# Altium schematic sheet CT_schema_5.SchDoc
size 309 x 321 mm
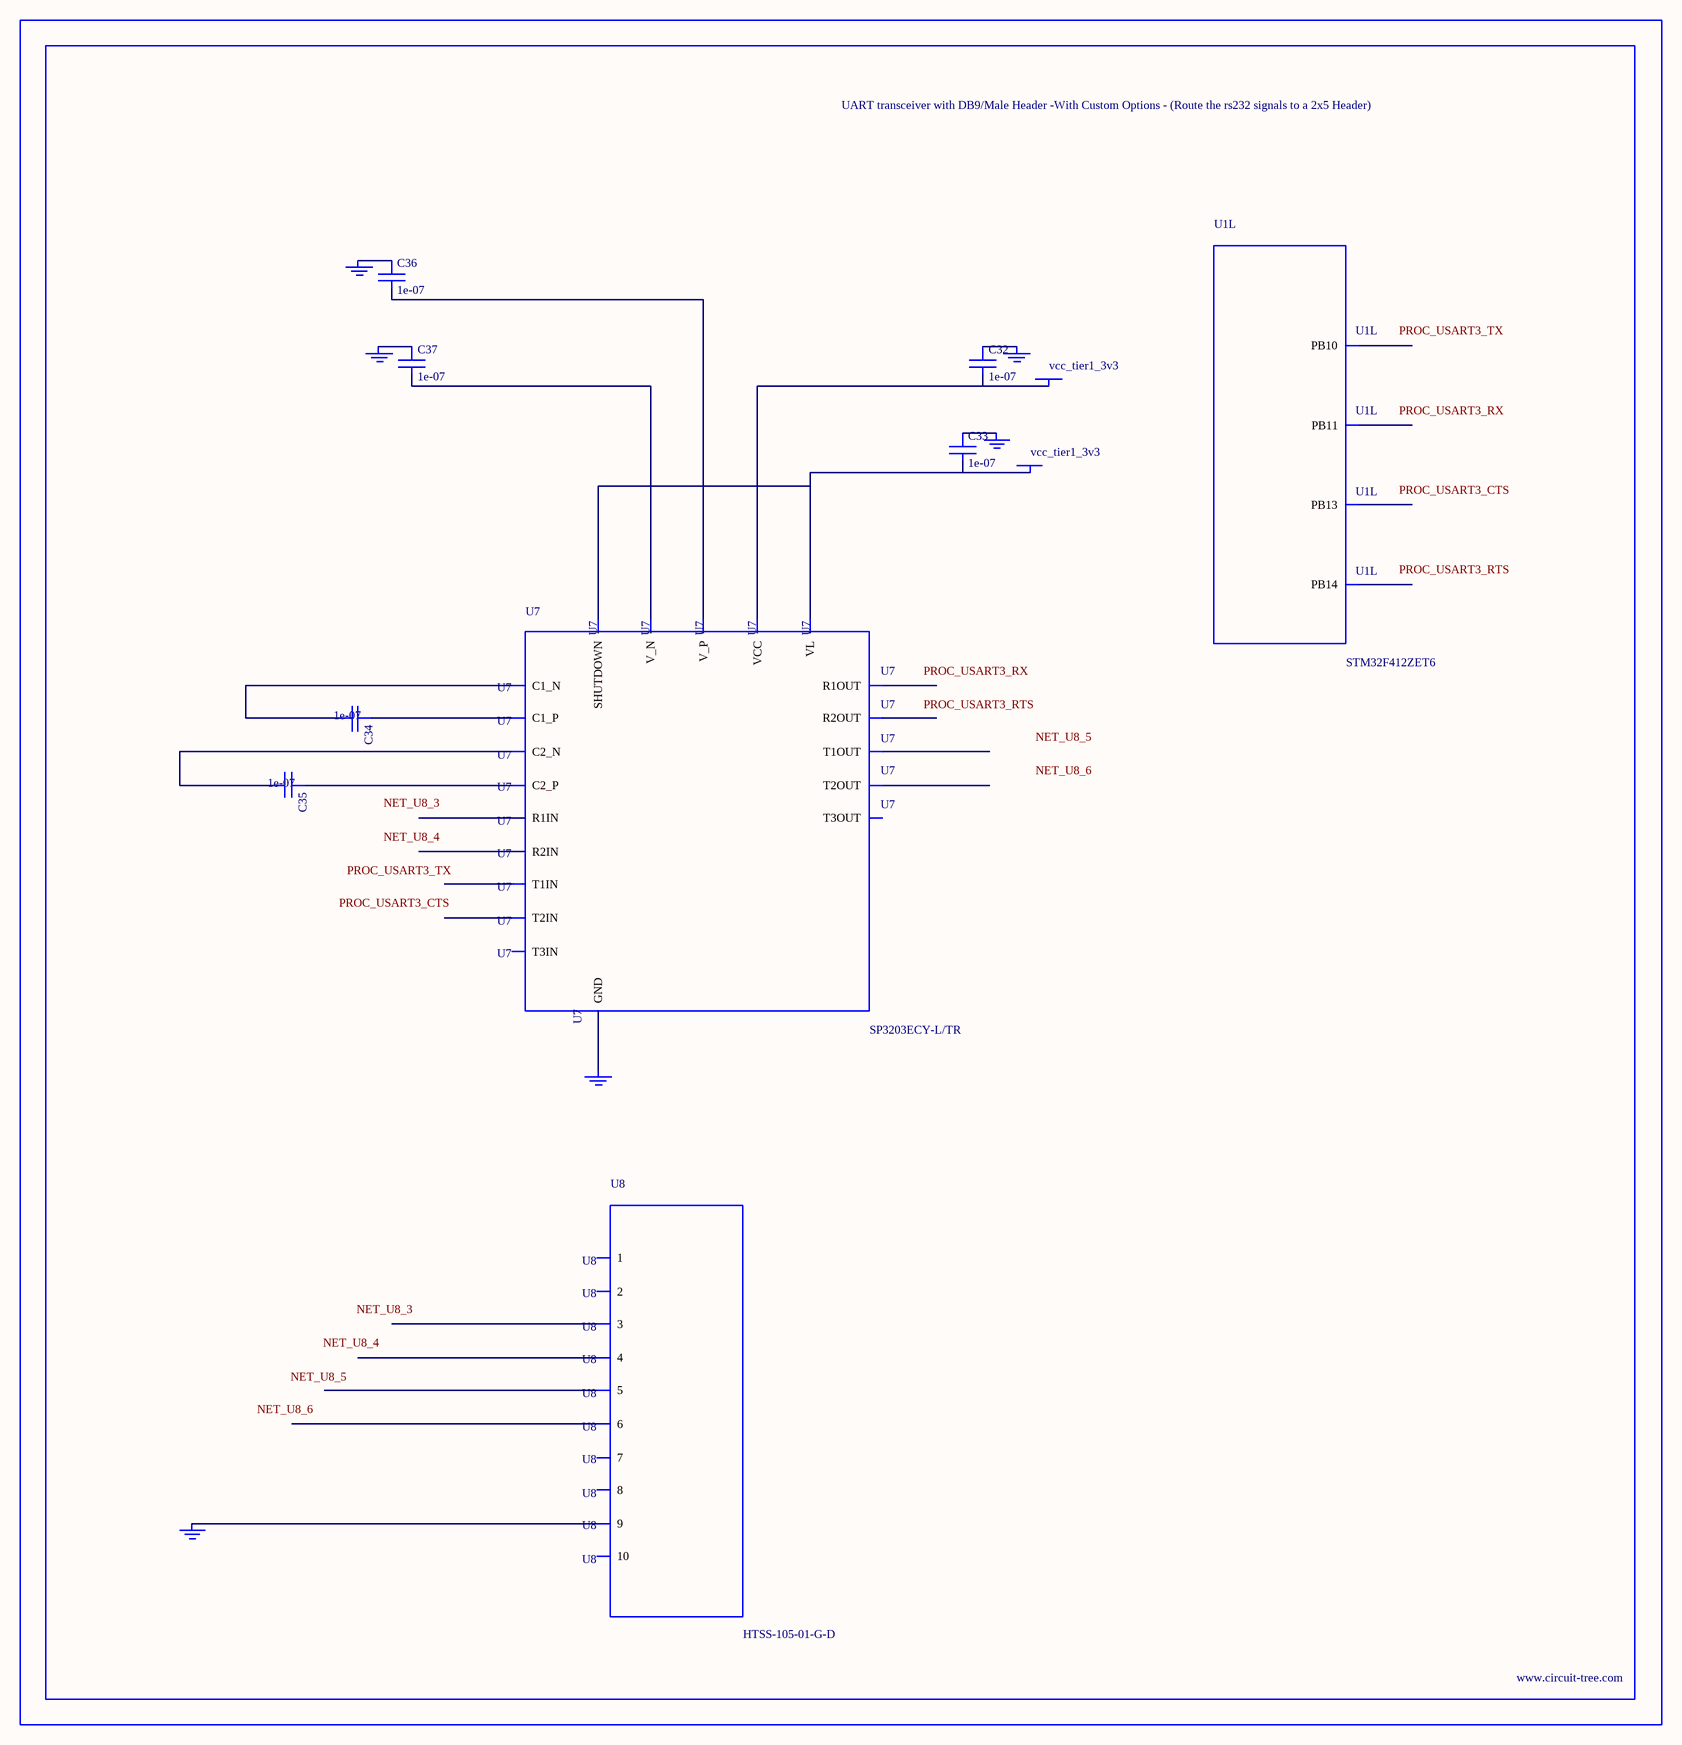
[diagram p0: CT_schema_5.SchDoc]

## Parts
BORDER4  (no value)
C32  1e-07  [C0402]
C33  1e-07  [C0402]
C34  1e-07  [C0402]
C35  1e-07  [C0402]
C36  1e-07  [C0402]
C37  1e-07  [C0402]
GND_INSTANCE_4_0  (no value)
GND_INSTANCE_4_1  (no value)
GND_INSTANCE_4_2  (no value)
GND_INSTANCE_4_3  (no value)
GND_INSTANCE_4_4  (no value)
GND_INSTANCE_4_5  (no value)
POWER_INSTANCE_4_0  vcc_tier1_3v3
POWER_INSTANCE_4_1  vcc_tier1_3v3
U1  STM32F412ZET6  [LQFP144]  (part L of 13)
U7  SP3203ECY-L/TR  [TSSOP20-I]
U8  HTSS-105-01-G-D  [HTSS-105-01-G-D]

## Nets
NetC32_1: C32.1 GND_INSTANCE_4_3.0(GND)
NetC32_2: C32.2 POWER_INSTANCE_4_1.0(PWR) U7.19(VCC)
NetC33_1: C33.1 GND_INSTANCE_4_2.0(GND)
NetC33_2: C33.2 POWER_INSTANCE_4_0.0(PWR) U7.12(VL) U7.20(SHUTDOWN)
NetC34_1: C34.1 U7.1(C1_P)
NetC34_2: C34.2 U7.3(C1_N)
NetC35_1: C35.1 U7.4(C2_P)
NetC35_2: C35.2 U7.5(C2_N)
NetC36_1: C36.1 GND_INSTANCE_4_0.0(GND)
NetC36_2: C36.2 U7.2(V_P)
NetC37_1: C37.1 GND_INSTANCE_4_1.0(GND)
NetC37_2: C37.2 U7.6(V_N)
NetGND_INSTANCE_4_4_0: GND_INSTANCE_4_4.0(GND) U7.18(GND)
NetGND_INSTANCE_4_5_0: GND_INSTANCE_4_5.0(GND) U8.9

Not connected (* = marked no-connect by the designer): U1 69(PB10) 70(PB11) 74(PB13) 75(PB14); U7 7(T1IN) 8(T2IN) 9(T3IN) 10(R2OUT) 11(R1OUT) 13(R2IN) 14(R1IN) 15(T3OUT) 16(T2OUT) 17(T1OUT); U8 1 2 3 4 5 6 7 8 10

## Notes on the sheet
- Labels drawn without touching a wire or pin: NET_U8_3, NET_U8_4, NET_U8_5, NET_U8_6, PROC_USART3_CTS, PROC_USART3_RTS, PROC_USART3_RX, PROC_USART3_TX

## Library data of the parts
BORDER4 = BORDER_PAGE4
C32-C37 = C0402C104K3RACTU
GND_INSTANCE_4_0-GND_INSTANCE_4_5 = GND
POWER_INSTANCE_4_0 POWER_INSTANCE_4_1 = PWR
